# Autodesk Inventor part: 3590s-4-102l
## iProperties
Created: 2017-05
Part Number: 3590s-4-102l
Checked By: TraceParts S.A.
Catalog Web Link: www.traceparts.com
Document SubType Name: Modeling
Designer: TraceParts
Company: TraceParts S.A.
Author: TraceParts
REFERENCE: 3590S-4-102L
DESIGN: Precision potentiometer 1K 22mm 10-turn
SUPPLIER: BOURNS
TraceParts.PartNumber: 10-18112016-088072
TraceParts.PartTitle: Precision potentiometer 1K 22mm 10-turn
TraceParts.InstanceId: 10-18112016-0880725HYJIHTSGDIG9XQ5AQQ7I76CU
TraceParts.PartStatus: Published
TraceParts.PartVersion: 1.0.0
TRACEPARTS: TRACEPARTS
TraceParts.PartLanguage: en
TraceParts.ClassPath: BOURNS:/F_BOURNS/10-18112016-088072
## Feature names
1. 3590s-4-102l
